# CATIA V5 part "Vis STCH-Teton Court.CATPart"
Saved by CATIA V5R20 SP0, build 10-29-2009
Part number: Vis STHC-Teton Court M 2x3
Material "Acier": density 7860 kg/m3, Young's modulus 2e+11 Pa, Poisson ratio 0.266, thermal expansion 1.17e-05 1/K
Bounding box of the stored display mesh (mm): x -0.983 to 0.983, y -0.992 to 0.992, z 0 to 3
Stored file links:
  C:\travail\CAO\bib catia\vis\Vis STCH-Teton Court.CATPart
  C:\Program Files\Dassault Systemes\B20\win_b64\startup\materials\French\Catalog.CATMaterial
  C:\Program Files\Dassault Systemes\B20\win_b64\reffiles\standard\MetricThickPitch.txt
  C:\travail\CAO\bib catia\vis\vis-HTSC_BP.xls
  C:\travail\CAO\bib catia\vis\vis-HTSC_BC.xls
  C:\travail\CAO\bib catia\vis\vis-HTSC_TL.xls
  C:\travail\CAO\bib catia\vis\vis-HTSC_TC.xls
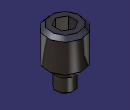
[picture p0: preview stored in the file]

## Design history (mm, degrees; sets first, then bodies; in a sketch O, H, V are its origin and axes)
Parameters
  d = 2 mm {design table}
  dp = 1 mm {design table}
  t = 1.7 mm {design table}
  s = 0.9 mm {design table}
  p = 0.4 mm {design table}
  l = 3 mm {design table}
  Designation = "Vis STHC-Teton Court M 2x3" {design table}
  dn = "M2" {design table}
  tc = 0.75 mm {design table}
Body1 (main body)
  Sketch1 on yz-plane, origin (0, 0, 0), H (0, 1, 0), V (0, 0, 1)
    axis line L1 (0, 0) -> (0, 10.0456)
    line L2 (0, 0) -> (-0.5, 0)
    point P2 (-0.5, 0)
    line L3 (-0.5, 0) -> (-0.5, 0.75)
    line L4 (-1, 0.75) -> (-1, 3)
    line L5 (-1, 3) -> (0, 3)
    point P4 (0, 3)
    line L6 (0, 3) -> (0, 0)
    line L7 (-1, 0.75) -> (-0.5, 0.75)
    "Radius" L4 L1 = 1 {= d /2}
    distance L2 L5 = 3 {= l}
    "Radius" P2 L1 = 0.5 {= dp /2}
    length L3 = 0.75 {= tc}
    vertical: L1 V, L4 V, L6 V, L3 V
    horizontal: L2 H, L5 H, L7 H
    coincidence: P4 L1
  Shaft1: profile Sketch1, axis Sketch1.L1, angle 360
  Thread1: "M2", diameter 2, depth 2.25, pitch 0.4, on face of Shaft1 from Sketch1.L4, from face of Shaft1 from Sketch1.L5
  Chamfer1: length 0.2 {= p /2}, angle 45, on edge [face of Shaft1 from Sketch1.L4 | face of Shaft1 from Sketch1.L5]
  Sketch2 on face of Shaft1 from Sketch1.L5, origin (0, 0, 3), H (1, 0, 0), V (0, 1, 0)
    point P1 (0, 0)
    point P2 (0.45, -0.2598)
    point P3 (0.45, 0.2598)
    point P4 (0, 0.5196)
    point P5 (-0.45, 0.2598)
    point P6 (-0.45, -0.2598)
    point P7 (0, -0.5196)
    point P8 (0.45, 0)
    line L1 (0.45, -0.2598) -> (0.45, 0.2598)
    line L2 (0.45, 0.2598) -> (0, 0.5196)
    line L3 (0, 0.5196) -> (-0.45, 0.2598)
    line L4 (-0.45, 0.2598) -> (-0.45, -0.2598)
    line L5 (-0.45, -0.2598) -> (0, -0.5196)
    line L6 (0, -0.5196) -> (0.45, -0.2598)
    construction line L7 (0, 0) -> (0.45, 0)
    construction circle A1 centre (0, 0) radius 0.5196
    construction arc A2 centre (-0.45, -0.2598) radius 0.5196 from (-0.45, 0.2598) to (0, -0.5196) cw
    construction arc A3 centre (0.45, 0.2598) radius 0.5196 from (0, 0.5196) to (0.45, -0.2598) ccw
    distance L4 L1 = 0.9 {= s}
    coincidence: P1 H, A1 P2, A1 P3, A1 P4, A1 P5, A1 P6, A1 P7, A2 P1, A3 P1, P1 O
    horizontal: L7 H
    midpoint: P8 L1
  Pocket1: profile Sketch2, direction (0, 0, -1), length 1.7 {= t}
  Chamfer2: length 0.5 {= d /2 - dp /2}, angle 45, on edge [face of Shaft1 from Sketch1.L7 | face of Shaft1 from Sketch1.L4]
  Chamfer3: length 0.04 {= p /10}, angle 45, on edge [face of Shaft1 from Sketch1.L2 | face of Shaft1 from Sketch1.L3]
Relations
  Thread1.ThreadDescription = dn
  design table, configuration 1, drives dn, d, p, dp, s, t, tc, l, Designation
